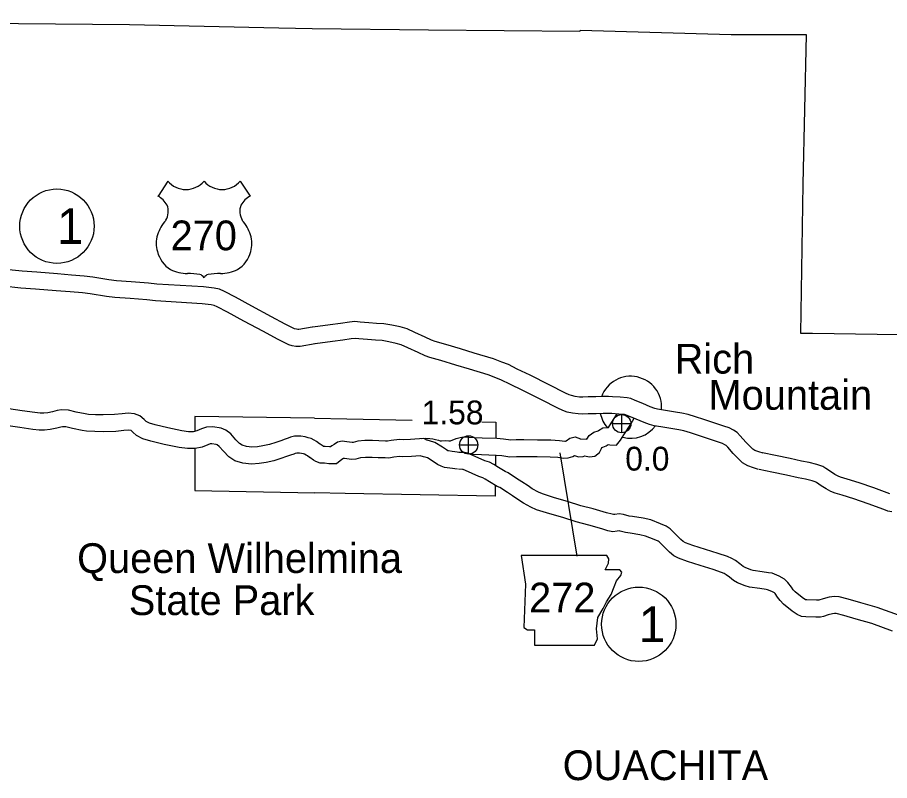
# Model space of a CAD drawing. Extents: x -939622 to -934245, y 1383184 to 1385301.
# Drawn here: x -936434.76 to -936388.3, y 1384185.16 to 1384225.79 of the extents above; entities that cross this region are included whole.
import ezdxf

# ---------------------------------------------------------------- set-up
doc = ezdxf.new("R2010")
doc.units = 0
for name, color, linetype in [('10', 7, 'Continuous'), ('15', 7, 'Continuous'), ('2', 7, 'Continuous'), ('21', 7, 'Continuous'), ('22', 7, 'Continuous'), ('24', 7, 'Continuous'), ('25', 7, 'Continuous'), ('26', 7, 'Continuous'), ('27', 7, 'Continuous'), ('7', 7, 'Continuous'), ('8', 7, 'Continuous'), ('Level 2', 7, 'Continuous')]:
    doc.layers.add(name, color=color, linetype=linetype)

msp = doc.modelspace()

# ---------------------------------------------------------------- linework, layer by layer
at = {"layer": '10'}
for points in [[(-936418.663, 1384203.096), (-936418.823, 1384203.213), (-936418.946, 1384203.278), (-936419.12, 1384203.372), (-936419.277, 1384203.417), (-936419.437, 1384203.459), (-936419.661, 1384203.495), (-936419.823, 1384203.494), (-936419.992, 1384203.489), (-936420.208, 1384203.437), (-936420.331, 1384203.397), (-936420.505, 1384203.337), (-936420.726, 1384203.257), (-936421, 1384203.159), (-936421.335, 1384203.062), (-936421.68, 1384202.975), (-936421.977, 1384202.931), (-936422.264, 1384202.91), (-936422.565, 1384202.947), (-936422.792, 1384203.014), (-936422.925, 1384203.1), (-936423.122, 1384203.304), (-936423.393, 1384203.623), (-936423.665, 1384203.816), (-936423.912, 1384203.927), (-936424.358, 1384204), (-936424.689, 1384203.98), (-936424.954, 1384203.881), (-936425.197, 1384203.781), (-936425.404, 1384203.735), (-936425.649, 1384203.732), (-936426, 1384203.779), (-936426.754, 1384203.933), (-936427.417, 1384204.093), (-936427.723, 1384204.193), (-936427.902, 1384204.286), (-936428.011, 1384204.38), (-936428.239, 1384204.586), (-936428.523, 1384204.687), (-936428.857, 1384204.724), (-936429.187, 1384204.694), (-936429.593, 1384204.646), (-936430.191, 1384204.627), (-936430.599, 1384204.637), (-936430.977, 1384204.655), (-936431.148, 1384204.685), (-936431.637, 1384204.782), (-936432.047, 1384204.882), (-936432.418, 1384204.897), (-936432.64, 1384204.862), (-936432.886, 1384204.797), (-936433.148, 1384204.736), (-936433.359, 1384204.721), (-936433.549, 1384204.72), (-936433.835, 1384204.752), (-936434.509, 1384204.844), (-936435.225, 1384204.948)], [(-936413.002, 1384203.39), (-936412.791, 1384203.379), (-936412.624, 1384203.348), (-936412.49, 1384203.316), (-936412.331, 1384203.276), (-936412.239, 1384203.251), (-936412.171, 1384203.246), (-936411.976, 1384203.265), (-936411.776, 1384203.253), (-936411.694, 1384203.254), (-936411.657, 1384203.262), (-936411.593, 1384203.284), (-936411.384, 1384203.38), (-936411.171, 1384203.42), (-936410.998, 1384203.46), (-936410.748, 1384203.446), (-936410.435, 1384203.433), (-936410.005, 1384203.412), (-936409.218, 1384203.384), (-936408.866, 1384203.364), (-936408.471, 1384203.306), (-936408.192, 1384203.314), (-936407.78, 1384203.313), (-936407.055, 1384203.309), (-936406.345, 1384203.299), (-936405.881, 1384203.274), (-936405.603, 1384203.236), (-936405.566, 1384203.237), (-936405.559, 1384203.239), (-936405.533, 1384203.257), (-936405.326, 1384203.393), (-936405.048, 1384203.455), (-936404.769, 1384203.353), (-936404.752, 1384203.34), (-936404.463, 1384203.349), (-936404.419, 1384203.342), (-936404.31, 1384203.534), (-936404.061, 1384203.718), (-936403.829, 1384203.773), (-936403.825, 1384203.775), (-936403.799, 1384203.795), (-936403.58, 1384203.945), (-936403.293, 1384203.955), (-936403.28, 1384203.953), (-936403.225, 1384204.045), (-936402.849, 1384204.627), (-936402.811, 1384204.687)], [(-936410.656, 1384202.541), (-936410.476, 1384202.534), (-936410.043, 1384202.513), (-936409.259, 1384202.485), (-936408.957, 1384202.468), (-936408.524, 1384202.405), (-936408.18, 1384202.414), (-936407.783, 1384202.413), (-936407.064, 1384202.409), (-936406.376, 1384202.399), (-936405.965, 1384202.377), (-936405.649, 1384202.334), (-936405.429, 1384202.341), (-936405.172, 1384202.413), (-936405.08, 1384202.476), (-936404.877, 1384202.398), (-936404.621, 1384202.416), (-936404.533, 1384202.447), (-936404.525, 1384202.447), (-936404.456, 1384202.435), (-936404.281, 1384202.4), (-936404.001, 1384202.43), (-936403.746, 1384202.622), (-936403.64, 1384202.844), (-936403.623, 1384202.897), (-936403.57, 1384202.91), (-936403.389, 1384202.976), (-936403.298, 1384203.045), (-936403.192, 1384203.029), (-936402.851, 1384203.02), (-936402.635, 1384203.277), (-936402.46, 1384203.57), (-936402.088, 1384204.145), (-936401.896, 1384204.455)], [(-936419.195, 1384202.37), (-936419.301, 1384202.448), (-936419.371, 1384202.484), (-936419.461, 1384202.533), (-936419.514, 1384202.548), (-936419.624, 1384202.577), (-936419.731, 1384202.594), (-936419.808, 1384202.594), (-936419.873, 1384202.592), (-936419.963, 1384202.571), (-936420.044, 1384202.544), (-936420.205, 1384202.489), (-936420.421, 1384202.411), (-936420.722, 1384202.303), (-936421.1, 1384202.193), (-936421.504, 1384202.091), (-936421.879, 1384202.036), (-936422.287, 1384202.006), (-936422.748, 1384202.063), (-936423.17, 1384202.187), (-936423.5, 1384202.4), (-936423.79, 1384202.699), (-936424.007, 1384202.955), (-936424.114, 1384203.031), (-936424.173, 1384203.058), (-936424.405, 1384203.096), (-936424.5, 1384203.09), (-936424.625, 1384203.043), (-936424.927, 1384202.919), (-936425.3, 1384202.837), (-936425.703, 1384202.832), (-936426.15, 1384202.891), (-936426.95, 1384203.055), (-936427.662, 1384203.227), (-936428.071, 1384203.36), (-936428.409, 1384203.535), (-936428.606, 1384203.704), (-936428.71, 1384203.798), (-936428.726, 1384203.804), (-936428.866, 1384203.819), (-936429.094, 1384203.799), (-936429.526, 1384203.748), (-936430.188, 1384203.727), (-936430.632, 1384203.738), (-936431.076, 1384203.759), (-936431.313, 1384203.8), (-936431.832, 1384203.903), (-936432.173, 1384203.987), (-936432.365, 1384203.994), (-936432.455, 1384203.98), (-936432.67, 1384203.923), (-936433.013, 1384203.844), (-936433.324, 1384203.821), (-936433.596, 1384203.82), (-936433.946, 1384203.858), (-936434.634, 1384203.953), (-936435.382, 1384204.061)], [(-936412.911, 1384203.264), (-936413.106, 1384203.381), (-936413.816, 1384203.317), (-936414.187, 1384203.303), (-936414.413, 1384203.328), (-936414.856, 1384203.269), (-936415.038, 1384203.235), (-936415.145, 1384203.239), (-936415.508, 1384203.251), (-936415.845, 1384203.261), (-936416.253, 1384203.262), (-936416.625, 1384203.227), (-936416.871, 1384203.167), (-936416.936, 1384203.162), (-936417.215, 1384203.193), (-936417.453, 1384203.231), (-936417.714, 1384203.175), (-936417.893, 1384203.062), (-936418.013, 1384202.978), (-936418.077, 1384202.926)], [(-936413.252, 1384203.368), (-936413.002, 1384203.39)], [(-936411.197, 1384202.628), (-936411.599, 1384202.682), (-936411.79, 1384202.71), (-936411.826, 1384202.723), (-936411.91, 1384202.767), (-936412.121, 1384202.91), (-936412.526, 1384203.157), (-936412.801, 1384203.254), (-936412.908, 1384203.276), (-936413.01, 1384203.308)], [(-936418.076, 1384202.933), (-936418.137, 1384202.933), (-936418.364, 1384202.952), (-936418.451, 1384202.953), (-936418.48, 1384202.973), (-936418.678, 1384203.106)], [(-936417.755, 1384202.031), (-936418.178, 1384202.033), (-936418.407, 1384202.053), (-936418.634, 1384202.055), (-936418.855, 1384202.141), (-936418.982, 1384202.226), (-936419.181, 1384202.36)], [(-936413.311, 1384202.459), (-936413.759, 1384202.418), (-936414.221, 1384202.402), (-936414.403, 1384202.422), (-936414.714, 1384202.38), (-936414.969, 1384202.333), (-936415.174, 1384202.339), (-936415.537, 1384202.352), (-936415.859, 1384202.361), (-936416.212, 1384202.362), (-936416.475, 1384202.337), (-936416.732, 1384202.274), (-936416.955, 1384202.259), (-936417.335, 1384202.301), (-936417.397, 1384202.311), (-936417.471, 1384202.259), (-936417.755, 1384202.031)], [(-936411.316, 1384201.736), (-936411.724, 1384201.791), (-936412.007, 1384201.832), (-936412.187, 1384201.896), (-936412.374, 1384201.994), (-936412.609, 1384202.154), (-936412.914, 1384202.34), (-936413.041, 1384202.385), (-936413.132, 1384202.403), (-936413.311, 1384202.459)], [(-936387.826, 1384193.96), (-936388.962, 1384194.373), (-936389.827, 1384194.624), (-936390.507, 1384194.817), (-936390.987, 1384194.939), (-936391.229, 1384194.959), (-936391.52, 1384194.931), (-936391.832, 1384194.834), (-936392.059, 1384194.761), (-936392.076, 1384194.757), (-936392.199, 1384194.758), (-936392.714, 1384194.775), (-936392.764, 1384194.779), (-936392.769, 1384194.781), (-936392.95, 1384194.908), (-936393.326, 1384195.209), (-936393.429, 1384195.319), (-936393.531, 1384195.455), (-936393.709, 1384195.711), (-936393.904, 1384195.889), (-936394.179, 1384196.045), (-936394.55, 1384196.196), (-936394.746, 1384196.228), (-936395.086, 1384196.274), (-936395.556, 1384196.338), (-936395.685, 1384196.38), (-936395.999, 1384196.502), (-936396.094, 1384196.56), (-936396.278, 1384196.703), (-936396.512, 1384196.875), (-936396.706, 1384196.99), (-936396.938, 1384197.089), (-936397.424, 1384197.249), (-936398.112, 1384197.467), (-936398.771, 1384197.673), (-936399.175, 1384197.824), (-936399.291, 1384197.884), (-936399.415, 1384197.988), (-936399.866, 1384198.44), (-936399.989, 1384198.561), (-936400.201, 1384198.707), (-936400.494, 1384198.826), (-936401.023, 1384199.036), (-936401.429, 1384199.136), (-936401.988, 1384199.217), (-936402.175, 1384199.244), (-936402.465, 1384199.329), (-936402.705, 1384199.362), (-936402.936, 1384199.332), (-936403.006, 1384199.322), (-936403.073, 1384199.337), (-936403.375, 1384199.423), (-936404.082, 1384199.626), (-936404.739, 1384199.797), (-936405.449, 1384200.022), (-936406.144, 1384200.222), (-936406.795, 1384200.421), (-936406.999, 1384200.513), (-936407.33, 1384200.701), (-936407.549, 1384200.849), (-936407.895, 1384201.071), (-936408.167, 1384201.248), (-936408.611, 1384201.539), (-936408.772, 1384201.619), (-936409.133, 1384201.827), (-936409.38, 1384201.991), (-936409.612, 1384202.109), (-936409.855, 1384202.193), (-936410.526, 1384202.489), (-936410.75, 1384202.588), (-936410.95, 1384202.624), (-936411.244, 1384202.632)], [(-936388.142, 1384193.117), (-936389.241, 1384193.517), (-936390.075, 1384193.759), (-936390.74, 1384193.948), (-936391.137, 1384194.048), (-936391.224, 1384194.056), (-936391.341, 1384194.044), (-936391.561, 1384193.976), (-936391.813, 1384193.895), (-936391.97, 1384193.856), (-936392.218, 1384193.858), (-936392.764, 1384193.876), (-936392.996, 1384193.895), (-936393.22, 1384193.999), (-936393.49, 1384194.187), (-936393.94, 1384194.547), (-936394.12, 1384194.741), (-936394.26, 1384194.928), (-936394.39, 1384195.114), (-936394.436, 1384195.156), (-936394.571, 1384195.233), (-936394.795, 1384195.324), (-936394.88, 1384195.338), (-936395.207, 1384195.383), (-936395.757, 1384195.457), (-936395.988, 1384195.532), (-936396.401, 1384195.693), (-936396.607, 1384195.819), (-936396.821, 1384195.985), (-936397.008, 1384196.123), (-936397.114, 1384196.186), (-936397.256, 1384196.246), (-936397.701, 1384196.393), (-936398.382, 1384196.609), (-936399.062, 1384196.821), (-936399.541, 1384197), (-936399.792, 1384197.13), (-936400.024, 1384197.323), (-936400.501, 1384197.802), (-936400.565, 1384197.865), (-936400.631, 1384197.91), (-936400.83, 1384197.991), (-936401.299, 1384198.177), (-936401.602, 1384198.252), (-936402.116, 1384198.326), (-936402.367, 1384198.362), (-936402.654, 1384198.447), (-936402.707, 1384198.454), (-936402.812, 1384198.44), (-936403.047, 1384198.406), (-936403.299, 1384198.466), (-936403.621, 1384198.557), (-936404.32, 1384198.758), (-936404.989, 1384198.932), (-936405.709, 1384199.16), (-936406.4, 1384199.359), (-936407.113, 1384199.577), (-936407.408, 1384199.71), (-936407.805, 1384199.937), (-936408.044, 1384200.098), (-936408.383, 1384200.315), (-936408.659, 1384200.495), (-936409.058, 1384200.756), (-936409.197, 1384200.825), (-936409.607, 1384201.062), (-936409.835, 1384201.213), (-936409.964, 1384201.279), (-936410.184, 1384201.354), (-936410.889, 1384201.666), (-936411.014, 1384201.721), (-936411.042, 1384201.726), (-936411.269, 1384201.732)]]:
    msp.add_lwpolyline(points, dxfattribs=at)
at = {"layer": '15'}
for points in [[(-936419.06, 1384209.297), (-936419.765, 1384209.17), (-936419.826, 1384209.172), (-936419.899, 1384209.187), (-936419.992, 1384209.215), (-936420.17, 1384209.292), (-936420.497, 1384209.456), (-936421.231, 1384209.856), (-936422.273, 1384210.414), (-936423.139, 1384210.89), (-936423.725, 1384211.201), (-936423.992, 1384211.317), (-936424.287, 1384211.385), (-936424.846, 1384211.445), (-936427.331, 1384211.595), (-936427.776, 1384211.647), (-936428.694, 1384211.72), (-936429.482, 1384211.771), (-936429.884, 1384211.826), (-936430.751, 1384211.962), (-936431.198, 1384212.019), (-936431.882, 1384212.078), (-936432.633, 1384212.136), (-936433.733, 1384212.222), (-936434.504, 1384212.276), (-936435.398, 1384212.379)], [(-936418.9, 1384208.412), (-936419.701, 1384208.267), (-936419.934, 1384208.275), (-936420.12, 1384208.314), (-936420.302, 1384208.369), (-936420.551, 1384208.476), (-936420.914, 1384208.659), (-936421.659, 1384209.065), (-936422.702, 1384209.623), (-936423.566, 1384210.098), (-936424.116, 1384210.389), (-936424.276, 1384210.459), (-936424.437, 1384210.496), (-936424.921, 1384210.548), (-936427.41, 1384210.698), (-936427.864, 1384210.751), (-936428.758, 1384210.822), (-936429.572, 1384210.874), (-936430.016, 1384210.936), (-936430.878, 1384211.071), (-936431.294, 1384211.124), (-936431.955, 1384211.181), (-936432.703, 1384211.238), (-936433.799, 1384211.325), (-936434.587, 1384211.38), (-936435.517, 1384211.487)], [(-936395.025, 1384202.596), (-936395.266, 1384202.666), (-936395.467, 1384202.736), (-936395.586, 1384202.804), (-936395.765, 1384202.974), (-936395.952, 1384203.179), (-936396.252, 1384203.524), (-936396.424, 1384203.694), (-936396.616, 1384203.823), (-936396.852, 1384203.942), (-936397.132, 1384204.038), (-936398.193, 1384204.389), (-936398.632, 1384204.531), (-936399.03, 1384204.656), (-936399.365, 1384204.726), (-936399.701, 1384204.78), (-936400.348, 1384204.881), (-936400.657, 1384204.931), (-936400.811, 1384204.972), (-936401.044, 1384205.062), (-936401.446, 1384205.23), (-936401.85, 1384205.399), (-936402.086, 1384205.496), (-936402.274, 1384205.541), (-936402.645, 1384205.575), (-936403.054, 1384205.6), (-936403.275, 1384205.608), (-936403.596, 1384205.603), (-936403.946, 1384205.583), (-936404.358, 1384205.583), (-936404.644, 1384205.575), (-936404.816, 1384205.581), (-936405.041, 1384205.613), (-936405.237, 1384205.655), (-936405.373, 1384205.697), (-936405.567, 1384205.793), (-936406.44, 1384206.236), (-936407.446, 1384206.745), (-936408.13, 1384207.071), (-936408.6, 1384207.306), (-936408.948, 1384207.445), (-936409.401, 1384207.61), (-936410.422, 1384207.925), (-936411.151, 1384208.146), (-936411.945, 1384208.382), (-936412.502, 1384208.545), (-936412.698, 1384208.617), (-936413.044, 1384208.773), (-936413.595, 1384209.02), (-936414.001, 1384209.209), (-936414.371, 1384209.313), (-936414.808, 1384209.412), (-936415.242, 1384209.481), (-936415.632, 1384209.501), (-936416.038, 1384209.533), (-936416.502, 1384209.572), (-936416.778, 1384209.595), (-936417.076, 1384209.567), (-936417.543, 1384209.503), (-936418.094, 1384209.43), (-936418.751, 1384209.341), (-936419.043, 1384209.3)], [(-936395.276, 1384201.731), (-936395.54, 1384201.808), (-936395.843, 1384201.914), (-936396.128, 1384202.077), (-936396.407, 1384202.343), (-936396.624, 1384202.58), (-936396.91, 1384202.909), (-936396.997, 1384202.995), (-936397.07, 1384203.044), (-936397.201, 1384203.11), (-936397.419, 1384203.185), (-936398.473, 1384203.533), (-936398.905, 1384203.673), (-936399.258, 1384203.784), (-936399.529, 1384203.841), (-936399.841, 1384203.891), (-936400.49, 1384203.992), (-936400.846, 1384204.05), (-936401.089, 1384204.115), (-936401.379, 1384204.226), (-936401.794, 1384204.4), (-936402.195, 1384204.568), (-936402.362, 1384204.637), (-936402.42, 1384204.65), (-936402.714, 1384204.677), (-936403.098, 1384204.701), (-936403.284, 1384204.708), (-936403.562, 1384204.703), (-936403.92, 1384204.683), (-936404.346, 1384204.683), (-936404.648, 1384204.675), (-936404.895, 1384204.683), (-936405.198, 1384204.726), (-936405.465, 1384204.783), (-936405.707, 1384204.858), (-936405.97, 1384204.988), (-936406.847, 1384205.433), (-936407.843, 1384205.937), (-936408.524, 1384206.262), (-936408.968, 1384206.484), (-936409.269, 1384206.604), (-936409.688, 1384206.757), (-936410.685, 1384207.065), (-936411.409, 1384207.284), (-936412.2, 1384207.518), (-936412.784, 1384207.69), (-936413.038, 1384207.783), (-936413.414, 1384207.952), (-936413.969, 1384208.202), (-936414.314, 1384208.362), (-936414.592, 1384208.44), (-936414.979, 1384208.528), (-936415.336, 1384208.585), (-936415.69, 1384208.602), (-936416.111, 1384208.636), (-936416.577, 1384208.675), (-936416.774, 1384208.691), (-936416.974, 1384208.673), (-936417.423, 1384208.611), (-936417.974, 1384208.538), (-936418.628, 1384208.45), (-936418.917, 1384208.409)], [(-936388.292, 1384200.431), (-936389.13, 1384200.745), (-936389.915, 1384201.017), (-936390.562, 1384201.214), (-936390.917, 1384201.318), (-936391.039, 1384201.364), (-936391.213, 1384201.465), (-936391.444, 1384201.616), (-936391.693, 1384201.777), (-936391.86, 1384201.891), (-936392.166, 1384201.988), (-936392.575, 1384202.095), (-936392.986, 1384202.169), (-936393.598, 1384202.304), (-936394.382, 1384202.468), (-936395.062, 1384202.605)], [(-936388.173, 1384199.464), (-936388.394, 1384199.51), (-936388.604, 1384199.587), (-936389.436, 1384199.898), (-936390.194, 1384200.161), (-936390.82, 1384200.352), (-936391.204, 1384200.465), (-936391.425, 1384200.548), (-936391.684, 1384200.697), (-936391.935, 1384200.861), (-936392.191, 1384201.027), (-936392.259, 1384201.073), (-936392.416, 1384201.123), (-936392.769, 1384201.215), (-936393.163, 1384201.286), (-936393.787, 1384201.424), (-936394.563, 1384201.586), (-936395.239, 1384201.722)]]:
    msp.add_lwpolyline(points, dxfattribs=at)
at = {"layer": '2'}
for points in [[(-936419.066, 1384225.193), (-936420.839, 1384225.228), (-936428.792, 1384225.39), (-936436.686, 1384225.473), (-936444.603, 1384225.544), (-936452.445, 1384225.565), (-936452.436, 1384225.712), (-936454.761, 1384225.791)], [(-936362.584, 1384208.458), (-936368.86, 1384208.592), (-936376.474, 1384208.747), (-936384.374, 1384208.84), (-936392.407, 1384208.956), (-936393.024, 1384208.972), (-936392.904, 1384216.908), (-936392.718, 1384224.863), (-936396.731, 1384224.86), (-936404.785, 1384225.099), (-936404.797, 1384225.038), (-936412.856, 1384225.109), (-936419.066, 1384225.193)]]:
    msp.add_lwpolyline(points, dxfattribs=at)
at = {"layer": '21'}
msp.add_line((-936405.859, 1384202.612), (-936404.963, 1384197.107), dxfattribs=at)
msp.add_lwpolyline([(-936407.917, 1384197.143), (-936407.689, 1384195.62), (-936407.791, 1384193.311), (-936407.588, 1384193.184), (-936407.207, 1384193.184), (-936407.207, 1384192.372), (-936404.009, 1384192.372), (-936403.857, 1384192.702), (-936403.908, 1384193.235), (-936403.832, 1384193.844), (-936403.553, 1384194.326), (-936403.375, 1384194.681), (-936403.121, 1384195.062), (-936402.969, 1384195.468), (-936402.842, 1384195.798), (-936402.614, 1384196.077), (-936402.563, 1384196.255), (-936402.664, 1384196.381), (-936403.451, 1384196.381), (-936403.273, 1384196.737), (-936403.248, 1384196.965), (-936403.353, 1384197.141)], close=True, dxfattribs=at)
at = {"layer": '22'}
for p, q in [((-936426.75, 1384217.081), (-936427.269, 1384216.278)), ((-936422.889, 1384217.081), (-936422.37, 1384216.278))]:
    msp.add_line(p, q, dxfattribs=at)
for centre, radius, start, end in [((-936425.783, 1384217.895), 1.264, 220.075, 319.6701), ((-936423.856, 1384217.895), 1.264, 220.3299, 319.925), ((-936427.948, 1384215.112), 1.349, 30.7809, 59.9883), ((-936421.691, 1384215.112), 1.349, 120.0117, 149.2191), ((-936427.651, 1384215.468), 0.925, 328.8105, 21.2108), ((-936421.988, 1384215.468), 0.925, 158.7892, 211.1895), ((-936425.233, 1384213.572), 2.157, 138.9565, 162.6913), ((-936424.407, 1384213.572), 2.157, 17.3087, 41.0435), ((-936425.945, 1384213.749), 1.426, 160.9576, 197.3819), ((-936423.694, 1384213.749), 1.426, 342.6181, 19.0424), ((-936425.713, 1384213.753), 1.65, 195.1074, 237.1312), ((-936423.927, 1384213.753), 1.65, 302.8688, 344.8926), ((-936425.682, 1384214.273), 2.118, 244.0771, 269.5779), ((-936425.633, 1384208.275), 3.88, 81.1942, 90.9539), ((-936425.148, 1384211.754), 0.372, 28.0342, 72.9864), ((-936424.491, 1384211.754), 0.372, 107.0136, 151.9658), ((-936424.006, 1384208.275), 3.88, 89.0461, 98.8058), ((-936423.957, 1384214.273), 2.118, 270.4221, 295.9229)]:
    msp.add_arc(centre, radius, start, end, dxfattribs=at)
at = {"layer": '24'}
for start, end in [(355.5516, 160.0848), (191.4365, 221.5128), (255.4485, 323.2286)]:
    msp.add_arc((-936402.091, 1384205.037), 1.65, start, end, dxfattribs=at)
at = {"layer": '26'}
for p, q in [((-936402.567, 1384203.677), (-936402.567, 1384204.652)), ((-936403.055, 1384204.164), (-936402.08, 1384204.164)), ((-936410.722, 1384202.544), (-936410.722, 1384203.519)), ((-936411.209, 1384203.032), (-936410.234, 1384203.032))]:
    msp.add_line(p, q, dxfattribs=at)
for centre in [(-936402.567, 1384204.164), (-936410.722, 1384203.032)]:
    msp.add_circle(centre, 0.487, dxfattribs=at)
at = {"layer": '27'}
for centre in [(-936432.656, 1384214.678), (-936401.657, 1384193.482)]:
    msp.add_circle(centre, 1.98, dxfattribs=at)
at = {"layer": '7'}
for points in [[(-936418.931, 1384204.462), (-936425.303, 1384204.536), (-936425.304, 1384203.748)], [(-936418.931, 1384204.462), (-936417.22, 1384204.423), (-936413.736, 1384204.342)], [(-936410.02, 1384204.255), (-936409.265, 1384204.237), (-936409.274, 1384203.415)], [(-936425.305, 1384202.832), (-936425.307, 1384200.609), (-936418.921, 1384200.484)], [(-936409.286, 1384202.483), (-936409.292, 1384201.97)], [(-936409.305, 1384200.883), (-936409.311, 1384200.295), (-936417.308, 1384200.447), (-936418.921, 1384200.484)]]:
    msp.add_lwpolyline(points, dxfattribs=at)
at = {"layer": 'Level 2'}
for points in [[(-936419.066, 1384225.193), (-936420.839, 1384225.228), (-936428.792, 1384225.39), (-936436.686, 1384225.473), (-936444.603, 1384225.544), (-936452.445, 1384225.565), (-936452.436, 1384225.712), (-936454.761, 1384225.791)], [(-936362.584, 1384208.458), (-936368.86, 1384208.592), (-936376.474, 1384208.747), (-936384.374, 1384208.84), (-936392.407, 1384208.956), (-936393.024, 1384208.972), (-936392.904, 1384216.908), (-936392.718, 1384224.863), (-936396.731, 1384224.86), (-936404.785, 1384225.099), (-936404.797, 1384225.038), (-936412.856, 1384225.109), (-936419.066, 1384225.193)]]:
    msp.add_lwpolyline(points, dxfattribs=at)

# ---------------------------------------------------------------- texts
at = {"layer": '21'}
msp.add_text('272', height=1.584, dxfattribs=at).set_placement((-936407.503, 1384194.113))
at = {"layer": '22'}
msp.add_text('270', height=1.584, dxfattribs=at).set_placement((-936426.602, 1384213.394))
at = {"layer": '24'}
for s, p in [('Rich', (-936399.749, 1384206.829)), ('Mountain', (-936397.941, 1384204.904))]:
    msp.add_text(s, height=1.584, dxfattribs=at).set_placement(p)
at = {"layer": '25'}
for s, p in [('1.58', (-936413.227, 1384204.127)), ('0.0', (-936402.38, 1384201.666))]:
    msp.add_text(s, height=1.2672, dxfattribs=at).set_placement(p)
at = {"layer": '27'}
for p in [(-936432.656, 1384213.728), (-936401.657, 1384192.531)]:
    msp.add_text('1', height=1.901, dxfattribs=at).set_placement(p)
at = {"layer": '7'}
for s, p in [('Queen Wilhelmina', (-936431.58, 1384196.212)), ('State Park', (-936428.827, 1384193.973))]:
    msp.add_text(s, height=1.584, dxfattribs=at).set_placement(p)
at = {"layer": '8'}
msp.add_text('OUACHITA', height=1.584, dxfattribs=at).set_placement((-936405.71, 1384185.184))

doc.saveas('drawing.dxf')
